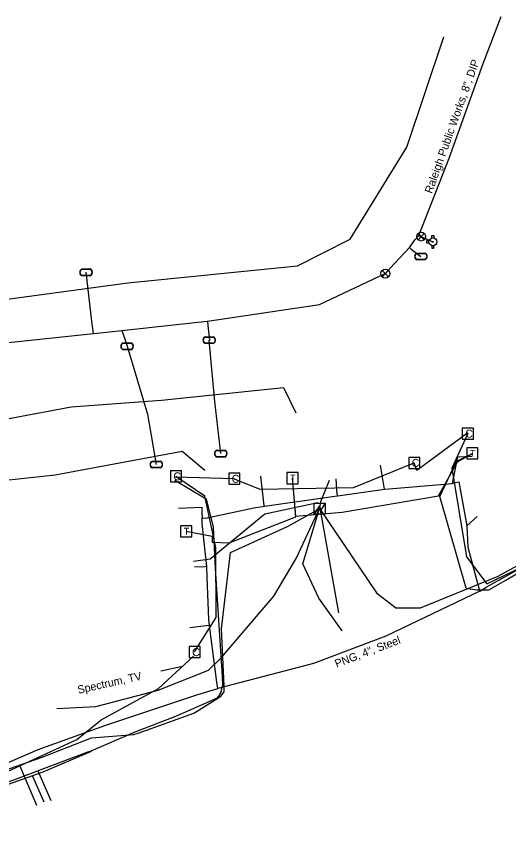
# Model space of a CAD drawing. Extents: x 2070721 to 2083039, y 729290 to 737883.
# Drawn here: x 2080033.2 to 2080279.4, y 734871.6 to 735280.8 of the extents above; entities that cross this region are included whole.
import ezdxf

# ---------------------------------------------------------------- set-up
doc = ezdxf.new("R2010")
doc.units = 0
for name, color, linetype in [('Cogo Default Point CELL', 7, 'Continuous'), ('COGO Default Point Elevation', 7, 'Continuous'), ('COGO Default Point Number', 7, 'Continuous'), ('Exist Utilities Gas UG Line SUE Cogo Point CELL', 7, 'Continuous'), ('Exist Utilities Gas Valve CELL', 7, 'Continuous'), ('Exist Utilities Power Pole Cogo Elevation', 7, 'Continuous'), ('Exist Utilities Telephone Hand Hole Cogo Elevation', 7, 'Continuous'), ('Exist Utilities Telephone UG Cable SUE LOS C Cogo Number', 7, 'Continuous'), ('Exist Utilities Telephone UG FO Cogo Point CELL', 7, 'Continuous'), ('Exist Utilities Telephone UG FO SUE LOS B Cogo Comment', 7, 'Continuous'), ('Exist Utilities TV Pedestal Cogo Elevation', 7, 'Continuous'), ('Exist Utilities TV Pedestal Cogo Number', 7, 'Continuous'), ('Exist Utilities TV UG Cable Cogo Point CELL', 7, 'Continuous'), ('Exist Utilities TV UG Cable SUE LOS C Cogo Comment', 7, 'Continuous'), ('Exist Utilities TV UG Cable SUE LOS C Cogo Elevation', 7, 'Continuous'), ('Exist Utilities Water Manhole CELL', 7, 'Continuous'), ('Exist Utilities Water Meter Cogo Elevation', 7, 'Continuous')]:
    doc.layers.add(name, color=color, linetype=linetype)

msp = doc.modelspace()

# ---------------------------------------------------------------- linework, layer by layer
at = {"layer": 'Cogo Default Point CELL'}
for p, q in [((2080259.02, 735072.36), (2080259.02, 735072.36)), ((2080232.23, 735057.76), (2080232.23, 735057.76)), ((2080113.05, 735051.03), (2080113.05, 735051.03)), ((2080142.2, 735049.83), (2080142.2, 735049.83)), ((2080122.45, 734963.25), (2080122.45, 734963.25))]:
    msp.add_line(p, q, dxfattribs=at)
for points in [[(2080256.25, 735069.59), (2080261.8, 735069.59), (2080261.8, 735075.14), (2080256.25, 735075.14), (2080256.25, 735069.59)], [(2080229.46, 735054.99), (2080235.01, 735054.99), (2080235.01, 735060.54), (2080229.46, 735060.54), (2080229.46, 735054.99)], [(2080110.28, 735048.26), (2080115.83, 735048.26), (2080115.83, 735053.81), (2080110.28, 735053.81), (2080110.28, 735048.26)], [(2080139.43, 735047.06), (2080144.98, 735047.06), (2080144.98, 735052.61), (2080139.43, 735052.61), (2080139.43, 735047.06)], [(2080119.67, 734960.48), (2080125.22, 734960.48), (2080125.22, 734966.03), (2080119.67, 734966.03), (2080119.67, 734960.48)]]:
    msp.add_lwpolyline(points, dxfattribs=at)
at = {"layer": 'COGO Default Point Elevation'}
for points in [[(2080237.25, 735172.42), (2080234.1, 735169.27), (2080235.68, 735170.85), (2080237.25, 735169.27), (2080234.1, 735172.42)], [(2080219.32, 735153.93), (2080216.17, 735150.78), (2080217.75, 735152.35), (2080219.32, 735150.78), (2080216.17, 735153.93)]]:
    msp.add_lwpolyline(points, dxfattribs=at)
for centre in [(2080235.68, 735170.85), (2080217.75, 735152.35)]:
    msp.add_circle(centre, 2.23, dxfattribs=at)
at = {"layer": 'COGO Default Point Number'}
msp.add_line((2080241.55, 735168.21), (2080241.55, 735168.21), dxfattribs=at)
for points in [[(2080241.04, 735170.12), (2080241.04, 735171.41), (2080242.07, 735171.41), (2080242.07, 735170.1)], [(2080239.64, 735168.72), (2080238.35, 735168.72), (2080238.35, 735167.7), (2080239.64, 735167.7)], [(2080241.04, 735166.3), (2080241.04, 735165.01), (2080242.07, 735165.01), (2080242.07, 735166.32)]]:
    msp.add_lwpolyline(points, dxfattribs=at)
for radius in [1.98, 0.243]:
    msp.add_circle((2080241.55, 735168.21), radius, dxfattribs=at)
at = {"layer": 'Exist Utilities Gas Valve CELL'}
for p, q in [((2080034.78, 734906.79), (2080043.22, 734886.76)), ((2080041.28, 734901.2), (2080047.01, 734888.42)), ((2080043.91, 734903.9), (2080050.53, 734889.18))]:
    msp.add_line(p, q, dxfattribs=at)
at = {"layer": 'Exist Utilities Power Pole Cogo Elevation'}
msp.add_lwpolyline([(2080184.91, 735034.97), (2080213.27, 734992.91), (2080223.08, 734985.41), (2080235.33, 734985.41), (2080274.11, 735001.25), (2080312.76, 735022.46), (2080338.71, 735040.35), (2080379.32, 735071.17)], dxfattribs=at)
at = {"layer": 'Exist Utilities Telephone UG Cable SUE LOS C Cogo Number'}
msp.add_line((2080185, 735035.1), (2080185, 735035.1), dxfattribs=at)
msp.add_lwpolyline([(2080182.15, 735037.71), (2080187.7, 735037.71), (2080187.7, 735032.16), (2080182.15, 735032.16)], close=True, dxfattribs=at)
for points in [[(2080182.15, 735032.16), (2080184.8, 735036.1), (2080185.42, 735033.89), (2080187.7, 735037.71)], [(2080182.22, 735032.16), (2080184.8, 735035.89), (2080185.38, 735033.71), (2080187.7, 735037.56)]]:
    msp.add_lwpolyline(points, dxfattribs=at)
at = {"layer": 'Exist Utilities Telephone UG FO Cogo Point CELL'}
for p, q in [((2080235.56, 735160.9), (2080235.56, 735160.9)), ((2080068.08, 735152.97), (2080068.08, 735152.97)), ((2080129.7, 735119.09), (2080129.7, 735119.09)), ((2080088.6, 735116), (2080088.6, 735116)), ((2080135.46, 735062.41), (2080135.46, 735062.41)), ((2080103.23, 735056.96), (2080103.23, 735056.96))]:
    msp.add_line(p, q, dxfattribs=at)
for points in [[(2080233.53, 735162.6), (2080237.6, 735162.6)], [(2080233.53, 735162.46), (2080237.6, 735162.46)], [(2080237.6, 735159.34), (2080233.5, 735159.34)], [(2080237.6, 735159.2), (2080233.5, 735159.2)], [(2080066.04, 735154.67), (2080070.11, 735154.67)], [(2080066.04, 735154.53), (2080070.11, 735154.53)], [(2080070.11, 735151.41), (2080066.01, 735151.41)], [(2080070.11, 735151.27), (2080066.01, 735151.27)], [(2080086.56, 735117.7), (2080090.63, 735117.7)], [(2080086.56, 735117.56), (2080090.63, 735117.56)], [(2080131.74, 735117.53), (2080127.64, 735117.53)], [(2080131.74, 735117.39), (2080127.64, 735117.39)], [(2080127.66, 735120.79), (2080131.74, 735120.79)], [(2080127.66, 735120.66), (2080131.74, 735120.66)], [(2080090.63, 735114.43), (2080086.53, 735114.43)], [(2080090.63, 735114.3), (2080086.53, 735114.3)], [(2080133.43, 735064.11), (2080137.5, 735064.11)], [(2080133.43, 735063.97), (2080137.5, 735063.97)], [(2080137.5, 735060.84), (2080133.4, 735060.84)], [(2080137.5, 735060.71), (2080133.4, 735060.71)], [(2080101.19, 735058.66), (2080105.27, 735058.66)], [(2080101.19, 735058.52), (2080105.27, 735058.52)], [(2080105.27, 735055.39), (2080101.17, 735055.39)], [(2080105.27, 735055.26), (2080101.17, 735055.26)]]:
    msp.add_lwpolyline(points, dxfattribs=at)
for centre, radius, start, end in [((2080234.26, 735160.89), 1.86, 113.178, 245.9794), ((2080234.27, 735160.89), 1.73, 115.3009, 243.7824), ((2080236.86, 735160.9), 1.86, 293.6483, 66.3084), ((2080236.87, 735160.9), 1.73, 295.1272, 64.8728), ((2080066.77, 735152.96), 1.86, 113.178, 245.9794), ((2080066.78, 735152.96), 1.73, 115.3009, 243.7824), ((2080069.37, 735152.97), 1.86, 293.6483, 66.3084), ((2080069.38, 735152.97), 1.73, 295.1272, 64.8728), ((2080087.29, 735115.99), 1.86, 113.178, 245.9794), ((2080087.3, 735115.99), 1.73, 115.3009, 243.7824), ((2080089.89, 735116), 1.86, 293.6483, 66.3084), ((2080089.9, 735116), 1.73, 295.1272, 64.8728), ((2080128.39, 735119.09), 1.86, 113.178, 245.9794), ((2080128.4, 735119.09), 1.73, 115.3009, 243.7824), ((2080130.99, 735119.09), 1.86, 293.6483, 66.3084), ((2080131, 735119.09), 1.73, 295.1272, 64.8728), ((2080134.16, 735062.4), 1.86, 113.178, 245.9794), ((2080134.17, 735062.4), 1.73, 115.3009, 243.7824), ((2080136.76, 735062.41), 1.86, 293.6483, 66.3084), ((2080136.77, 735062.41), 1.73, 295.1272, 64.8728), ((2080101.92, 735056.95), 1.86, 113.178, 245.9794), ((2080101.93, 735056.95), 1.73, 115.3009, 243.7824), ((2080104.52, 735056.96), 1.86, 293.6483, 66.3084), ((2080104.53, 735056.96), 1.73, 295.1272, 64.8728)]:
    msp.add_arc(centre, radius, start, end, dxfattribs=at)
at = {"layer": 'Exist Utilities Telephone UG FO SUE LOS B Cogo Comment'}
for p, q in [((2080261.2, 735062.55), (2080261.2, 735062.55)), ((2080171.26, 735050.19), (2080171.26, 735050.19)), ((2080118.07, 735023.62), (2080118.07, 735023.62))]:
    msp.add_line(p, q, dxfattribs=at)
for points in [[(2080258.48, 735059.73), (2080264.07, 735059.73), (2080264.07, 735065.32), (2080258.48, 735065.32), (2080258.48, 735059.73)], [(2080168.53, 735047.37), (2080174.13, 735047.37), (2080174.13, 735052.96), (2080168.53, 735052.96), (2080168.53, 735047.37)], [(2080115.35, 735020.79), (2080120.94, 735020.79), (2080120.94, 735026.39), (2080115.35, 735026.39), (2080115.35, 735020.79)]]:
    msp.add_lwpolyline(points, dxfattribs=at)
at = {"layer": 'Exist Utilities TV Pedestal Cogo Elevation'}
for points in [[(2080234.43, 735171.42), (2080249.6, 735209.95), (2080266.63, 735257.33), (2080275.66, 735280.84)], [(2080229.77, 735165.3), (2080230.67, 735166.49), (2080232.65, 735169.41), (2080234.43, 735171.42)], [(2080234.43, 735171.42), (2080238.14, 735169.72), (2080241.59, 735168.23)], [(2080234.44, 735171.44), (2080234.91, 735171.19)], [(2080128.81, 735128.56), (2080184.91, 735136.98), (2080217.74, 735152.32), (2080229.77, 735165.3)], [(2080229.77, 735165.3), (2080230.71, 735164.59), (2080235.55, 735160.96)], [(2080071.74, 735122.47), (2080071.01, 735128.57), (2080068.07, 735152.99)], [(2080086.04, 735123.83), (2080124.02, 735128.1), (2080128.81, 735128.56)], [(2080128.81, 735128.56), (2080128.91, 735126.35), (2080129.76, 735119.16)], [(2079937.59, 735108.95), (2079940.07, 735109.15), (2079994.44, 735114.29), (2080071.74, 735122.47)], [(2080071.91, 735122.43), (2080079.84, 735123.28), (2080086.04, 735123.83)], [(2080086.04, 735123.83), (2080086.61, 735122.16), (2080088.69, 735116.05)], [(2080135.46, 735062.4), (2080132.54, 735088.49), (2080129.7, 735119.09)], [(2080088.6, 735116), (2080098.77, 735082.1), (2080103.06, 735056.97)]]:
    msp.add_lwpolyline(points, dxfattribs=at)
at = {"layer": 'Exist Utilities TV Pedestal Cogo Number'}
for points in [[(2080265, 734993.65), (2080268.16, 734995.62), (2080315.96, 735022.08), (2080350.22, 735046.21), (2080381.14, 735070.17), (2080396.65, 735089.25), (2080394.64, 735105.68)], [(2080251.38, 735047.5), (2080251.53, 735048.23), (2080253.98, 735060.75), (2080261.09, 735061.09)], [(2080192.42, 735041.08), (2080194, 735041.25), (2080217.37, 735044.63), (2080215.3, 735056.61)], [(2080157.27, 735036.17), (2080157.2, 735036.33), (2080155.44, 735051.07)], [(2080194, 735041.25), (2080193.72, 735042.02), (2080193.14, 735049.84)], [(2080217.46, 735044.57), (2080251.38, 735047.5), (2080252.7, 735047.95)], [(2080252.7, 735047.95), (2080254.46, 735048.32), (2080258.49, 735026.31), (2080263.75, 735030.96)], [(2080157.27, 735036.17), (2080192.42, 735041.08)], [(2080114.31, 735035.09), (2080125.97, 735035.69), (2080126.02, 735032.77), (2080126.13, 735030.24)], [(2080126.13, 735030.24), (2080127.83, 735030.22), (2080151.99, 735035.25), (2080157.27, 735036.17)], [(2080128.42, 735006.06), (2080126.13, 735027.57), (2080126.13, 735030.24)], [(2080258.49, 735026.31), (2080258.94, 735015.59), (2080264.56, 734995.23), (2080265, 734993.65)], [(2080128.42, 735006.06), (2080126.73, 735005.69), (2080122.33, 735005.83)], [(2080129.49, 734979.47), (2080128.65, 735000.62), (2080128.42, 735006.06)], [(2080265, 734993.65), (2080217.97, 734971.17), (2080181.86, 734957.47), (2080133.94, 734945)], [(2080133.94, 734945), (2080133.53, 734948.19), (2080129.81, 734976.57), (2080129.49, 734979.47)], [(2080129.81, 734976.57), (2080128.22, 734976.37), (2080120.05, 734975.34)], [(2079949.32, 734879.97), (2079996.84, 734894.02), (2080044.13, 734914.6), (2080077.42, 734926.53), (2080123.41, 734941.95), (2080133.94, 734945)]]:
    msp.add_lwpolyline(points, dxfattribs=at)
at = {"layer": 'Exist Utilities TV UG Cable Cogo Point CELL'}
for points in [[(2080258.12, 734995.23), (2080263.29, 734994.32), (2080269.47, 734994.32), (2080277.96, 734999.19), (2080292.29, 735007.6), (2080305.23, 735017.65), (2080343.43, 735047.82), (2080360.16, 735059.94), (2080382.3, 735078.07), (2080399.75, 735092.65), (2080407.82, 735102.46), (2080410.57, 735111.53), (2080417.01, 735135.56), (2080418.86, 735142.51), (2080417.06, 735145.72), (2080413.79, 735150.42), (2080384.27, 735150.47)], [(2080171.24, 735050.15), (2080172.84, 735031.22), (2080196.21, 735033.14), (2080244.31, 735041.32), (2080253.84, 735058.25), (2080261.18, 735062.54)], [(2080258.12, 734995.23), (2080245, 735040.98), (2080253.37, 735058.59), (2080261.28, 735062.28)], [(2080118.09, 735023.61), (2080131.12, 735021.22), (2080131.12, 735018.18), (2080139.57, 735017.81), (2080172.95, 735030.85), (2080171.3, 735050.18)]]:
    msp.add_lwpolyline(points, dxfattribs=at)
at = {"layer": 'Exist Utilities TV UG Cable SUE LOS C Cogo Comment'}
for points in [[(2079821.33, 735124.13), (2079827.86, 735119.63), (2079874.94, 735123.38), (2079958.5, 735131.34), (2080015, 735137.74), (2080088.94, 735147.78), (2080173.89, 735156.26), (2080200.11, 735169.56), (2080228.49, 735215.43), (2080246.93, 735270.61)], [(2079970.93, 735068.94), (2080060.68, 735085.85), (2080105.85, 735089.11), (2080166.83, 735095.38), (2080172.93, 735082.78)], [(2079929, 735034.01), (2079966.1, 735042.55), (2080052.65, 735051.87), (2080116.2, 735063.66), (2080127.54, 735054.13)], [(2080112.49, 735049.08), (2080128.11, 735039.89), (2080131.69, 735025.59), (2080132.72, 735004.97), (2080136.13, 734951), (2080136.32, 734946.38)], [(2080185, 735035.24), (2080185.55, 735038.46), (2080189.91, 735049.2)], [(2080053.4, 734935.01), (2080073.04, 734936.04), (2080104.19, 734944.17), (2080129.31, 734954.23), (2080135.73, 734960.33), (2080162.03, 734991.2), (2080173.15, 735010.03), (2080185, 735035.24)], [(2080184.03, 735037.86), (2080157.46, 735032.17), (2080130.23, 735009.64), (2080121.75, 735008.46)], [(2080185.03, 735035.24), (2080190.32, 735005.32), (2080194.36, 734982.86)], [(2080137.09, 734946.33), (2080135.77, 734974.93), (2080140.28, 735012.96), (2080169.13, 735026.21), (2080185, 735035.04)], [(2080196.17, 734973.88), (2080184.49, 734990.15), (2080176.44, 735007.38), (2080184.91, 735034.97)], [(2079949.54, 734879.56), (2079979.11, 734882.53), (2079996.9, 734893.62), (2080046.16, 734910.81), (2080070.87, 734920.4), (2080091.91, 734922.1), (2080094.14, 734922.76), (2080121.97, 734932.67), (2080134.03, 734940.16), (2080135.53, 734941.3), (2080137.12, 734943.43), (2080137.09, 734946.33)], [(2079987.46, 734894.8), (2080025.82, 734897.12), (2080069.48, 734913.65), (2080069.5, 734913.41), (2080092.72, 734923.35), (2080113.03, 734931.23), (2080133.81, 734940.47), (2080134.5, 734941.28), (2080135.67, 734943.18), (2080136.32, 734946.38)], [(2080070.67, 734913.66), (2080046.49, 734903.28), (2080013.44, 734891.52), (2079979.04, 734880.46), (2079946.47, 734872.13), (2079941.84, 734871.56), (2079937.96, 734876.06)]]:
    msp.add_lwpolyline(points, dxfattribs=at)
at = {"layer": 'Exist Utilities TV UG Cable SUE LOS C Cogo Elevation'}
msp.add_line((2080142.28, 735049.86), (2080112.85, 735050.69), dxfattribs=at)
for points in [[(2080259.02, 735072.86), (2080233.57, 735054.03), (2080232.22, 735057.74)], [(2080259.06, 735072.37), (2080251.03, 735055.15), (2080258.34, 735010.88), (2080268.58, 734997.41), (2080290.37, 735007.91), (2080299.29, 735014.42), (2080347.12, 735048.66), (2080359.81, 735057.53)], [(2080142.2, 735049.82), (2080154.93, 735044.6), (2080201.85, 735045.5), (2080232.18, 735057.84)], [(2080122.39, 734963.3), (2080133.14, 734980.6), (2080132.95, 735015.54), (2080127.54, 735041.12), (2080113.06, 735051)], [(2079949.24, 734887.87), (2079959.74, 734898.59), (2079975.94, 734894.45), (2079996.9, 734893.38), (2080024.24, 734901.56), (2080063.46, 734919.58), (2080075.63, 734929.35), (2080104.34, 734945.04), (2080121.88, 734961.24)]]:
    msp.add_lwpolyline(points, dxfattribs=at)
at = {"layer": 'Exist Utilities Water Manhole CELL'}
msp.add_line((2080116.31, 734956.12), (2080105.53, 734953.77), dxfattribs=at)

# ---------------------------------------------------------------- texts
at = {"layer": 'Cogo Default Point CELL'}
for p in [(2080257.71, 735070.36), (2080230.93, 735055.76), (2080111.75, 735049.03), (2080140.9, 735047.83), (2080121.14, 734961.25)]:
    msp.add_text('C', height=4, dxfattribs=at).set_placement(p)
at = {"layer": 'Exist Utilities Gas UG Line SUE Cogo Point CELL'}
msp.add_text('Raleigh Public Works, 8", DIP ', height=4, rotation=70.2361, dxfattribs=at).set_placement((2080241.04, 735192.03))
at = {"layer": 'Exist Utilities Telephone Hand Hole Cogo Elevation'}
msp.add_text('Spectrum, TV ', height=4, rotation=12.6409, dxfattribs=at).set_placement((2080064.3, 734942.38))
at = {"layer": 'Exist Utilities Telephone UG FO SUE LOS B Cogo Comment'}
for p in [(2080260.07, 735060.84), (2080170.13, 735048.48), (2080116.94, 735021.91)]:
    msp.add_text('T', height=3.42, dxfattribs=at).set_placement(p)
at = {"layer": 'Exist Utilities Water Meter Cogo Elevation'}
msp.add_text('PNG, 4", Steel', height=4, rotation=20.7699, dxfattribs=at).set_placement((2080193.39, 734955.43))

doc.saveas('drawing.dxf')
